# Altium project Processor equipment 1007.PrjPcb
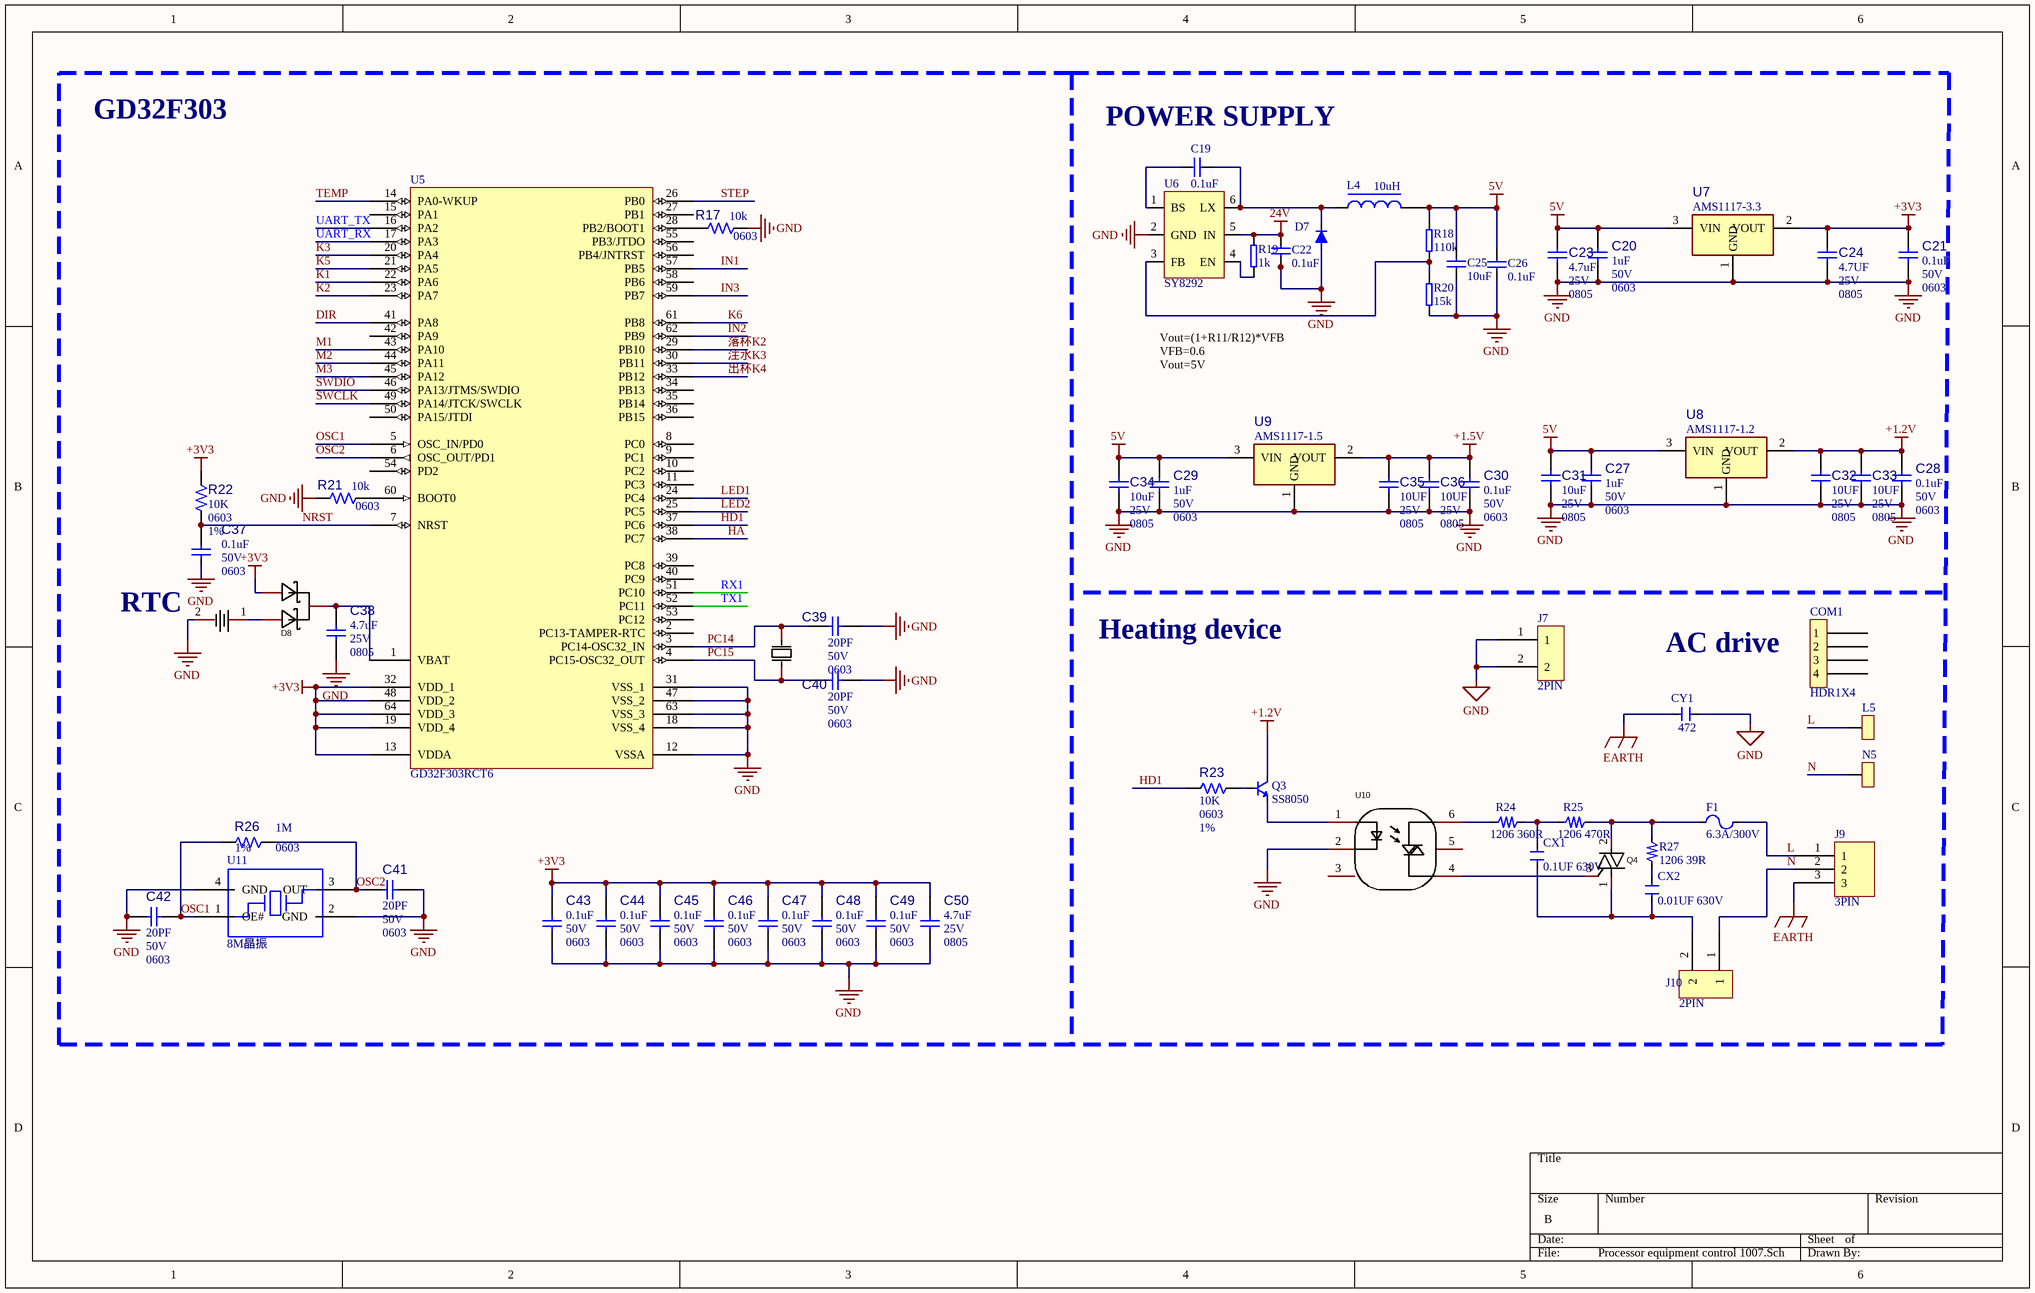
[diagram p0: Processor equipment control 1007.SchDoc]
3 sheets, 199 parts. Net scope: global (net labels, ports and power ports of the same name join across sheets).
Board file: Processor equipment 1101.PcbDoc
Sheets:
  Processor equipment control 1007.SchDoc
  Processor equipment drive 1007.SchDoc
  motor drive 1007.SchDoc

## Sheet Processor equipment control 1007.SchDoc
size B

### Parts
C19  0.1uF  [CAP_SMT_0805_T]
C20  value 1uF  Voltage: 50V  Package: 0603  [CAP_C_0603]  (hidden comment: Capacitor NP)
C21  value 0.1uF  Voltage: 50V  Package: 0603  [CAP_C_0603]  (hidden comment: Capacitor NP)
C22  0.1uF  [CAP_SMT_0805_T]
C23  value 4.7uF  Voltage: 25V  Package: 0805  [CAP_C_0805]  (hidden comment: Capacitor NP)
C24  value 4.7UF  Voltage: 25V  Package: 0805  [CAP_C_0805]  (hidden comment: Capacitor NP)
C25  10uF  [CAP_SMT_0805_T]
C26  0.1uF  [CAP_SMT_0805_T]
C27  value 1uF  Voltage: 50V  Package: 0603  [CAP_C_0603]  (hidden comment: Capacitor NP)
C28  value 0.1uF  Voltage: 50V  Package: 0603  [CAP_C_0603]  (hidden comment: Capacitor NP)
C29  value 1uF  Voltage: 50V  Package: 0603  [CAP_C_0603]  (hidden comment: Capacitor NP)
C30  value 0.1uF  Voltage: 50V  Package: 0603  [CAP_C_0603]  (hidden comment: Capacitor NP)
C31  value 10uF  Voltage: 25V  Package: 0805  [CAP_C_0805]  (hidden comment: Capacitor NP)
C32  value 10UF  Voltage: 25V  Package: 0805  [CAP_C_0805]  (hidden comment: Capacitor NP)
C33  value 10UF  Voltage: 25V  Package: 0805  [CAP_C_0805]  (hidden comment: Capacitor NP)
C34  value 10uF  Voltage: 25V  Package: 0805  [CAP_C_0805]  (hidden comment: Capacitor NP)
C35  value 10UF  Voltage: 25V  Package: 0805  [CAP_C_0805]  (hidden comment: Capacitor NP)
C36  value 10UF  Voltage: 25V  Package: 0805  [CAP_C_0805]  (hidden comment: Capacitor NP)
C37  value 0.1uF  Voltage: 50V  Package: 0603  [CAP_C_0603]  (hidden comment: Capacitor NP)
C38  value 4.7uF  Voltage: 25V  Package: 0805  [CAP_C_0805]  (hidden comment: Capacitor NP)
C39  value 20PF  Voltage: 50V  Package: 0603  [CAP_C_0603]  (hidden comment: Capacitor NP)
C40  value 20PF  Voltage: 50V  Package: 0603  [CAP_C_0603]  (hidden comment: Capacitor NP)
C41  value 20PF  Voltage: 50V  Package: 0603  [CAP_C_0603]  (hidden comment: Capacitor NP)
C42  value 20PF  Voltage: 50V  Package: 0603  [CAP_C_0603]  (hidden comment: Capacitor NP)
C43  value 0.1uF  Voltage: 50V  Package: 0603  [CAP_C_0603]  (hidden comment: Capacitor NP)
C44  value 0.1uF  Voltage: 50V  Package: 0603  [CAP_C_0603]  (hidden comment: Capacitor NP)
C45  value 0.1uF  Voltage: 50V  Package: 0603  [CAP_C_0603]  (hidden comment: Capacitor NP)
C46  value 0.1uF  Voltage: 50V  Package: 0603  [CAP_C_0603]  (hidden comment: Capacitor NP)
C47  value 0.1uF  Voltage: 50V  Package: 0603  [CAP_C_0603]  (hidden comment: Capacitor NP)
C48  value 0.1uF  Voltage: 50V  Package: 0603  [CAP_C_0603]  (hidden comment: Capacitor NP)
C49  value 0.1uF  Voltage: 50V  Package: 0603  [CAP_C_0603]  (hidden comment: Capacitor NP)
C50  value 4.7uF  Voltage: 25V  Package: 0805  [CAP_C_0805]  (hidden comment: Capacitor NP)
COM1  HDR1X4  [AC220v-24v]
CX1  0.1UF 630V  [C13*4*10_0.9]
CX2  0.01UF 630V  [C13*4*10_0.9]
CY1  472  [C9*6*7.5]
D7  US1K  [SMA-R]  (value not drawn)
D8  BAT54C-7-F  [SOT23-R-R]  (value not drawn)
F1  6.3A/300V  [FUSE_8.4*4.3_5.08_0.6]
J7  2PIN  [散热器]
J8  CR1220-2  [CR2032-6]  (value not drawn)
J9  3PIN  [HB-9500-3P]
J10  2PIN  [DG/KF128-2P]
L4  100016336  [100016336_SS_B]  (value not drawn)
L5  (no value)  [PAD_1.8]
N5  (no value)  [PAD_1.8]
Q3  SS8050  [SOT23-L-R]
Q4  BT138-800E  [TO-220-3_L10.0-W4.5-P2.54-L]  (value not drawn)
R17  value 10k  Package: 0603  [RES_C_0603]  (hidden comment: Resistor)
R18  110k  [RES_SMT_0805_T]
R19  1k  [RES_SMT_0805_T]
R20  15k  [RES_SMT_0805_T]
R21  value 10k  Package: 0603  [RES_C_0603]  (hidden comment: Resistor)
R22  value 10K  Package: 0603  Tolerance: 1%  [RES_C_0603]  (hidden comment: Resistor)
R23  value 10K  Package: 0603  Tolerance: 1%  [RES_C_0603]  (hidden comment: Resistor)
R24  1206 360R  [1206(3216)-R]
R25  1206 470R  [1206(3216)-R]
R26  value 1M  Package: 0603  Tolerance: 1%  [RES_C_0603]  (hidden comment: Resistor)
R27  1206 39R  [1206(3216)-R]
U5  GD32F303RCT6  [LQFP64]
U6  SY8292  [SOT23_6]
U7  value AMS1117-3.3  [SOT223-R]  (hidden comment: MCP1754ST-5002ECB SOT-23A-3)
U8  value AMS1117-1.2  [SOT223-R]  (hidden comment: MCP1754ST-5002ECB SOT-23A-3)
U9  value AMS1117-1.5  [SOT223-R]  (hidden comment: MCP1754ST-5002ECB SOT-23A-3)
U10  MOC3020SM_C3014297  [SOP-6_L7.1-W6.5-P2.54-LS10.1-BL]  (value not drawn)
U11  8M晶振  [S3225A]
X1  X50328MSB2GI  [X3215-2P晶振]  (value not drawn)

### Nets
5V: C20.2 C23.2 C25.1 C26.1 C27.2 C29.2 C31.2 C34.2 L4.2 R18.1 U7.3(VIN) U8.3(VIN) U9.3(VIN)
24V: C22.1 R19.2 U6.5(IN)
+1.2V: C28.2 C32.2 C33.2 Q3.3(C) U8.2(VOUT)
+1.5V: C30.2 C35.2 C36.2 U9.2(VOUT)
+3V3: C21.2 C24.2 C43.2 C44.2 C45.2 C46.2 C47.2 C48.2 C49.2 C50.2 D8.1(A) R22.2 U5.13(VDDA) U5.19(VDD_4) U5.32(VDD_1) U5.48(VDD_2) U5.64(VDD_3) U7.2(VOUT)
EARTH: CY1.2 J9.3
GND: C20.1 C21.1 C22.2 C23.1 C24.1 C25.2 C26.2 C27.1 C28.1 C29.1 C30.1 C31.1 C32.1 C33.1 C34.1 C35.1 C36.1 C37.1 C38.1 C39.1 C40.1 C41.1 C42.2 C43.1 C44.1 C45.1 C46.1 C47.1 C48.1 C49.1 C50.1 CY1.1 D7.1 J7.1 J7.2 J8.2 R17.1 R20.1 R21.2 U5.12(VSSA) U5.18(VSS_4) U5.31(VSS_1) U5.47(VSS_2) U5.63(VSS_3) U6.2(GND) U7.1(GND) U8.1(GND) U9.1(GND) U10.2(CAT) U11.2(GND) U11.4(GND)
DIR: U5.41(PA8)
HA: U5.38(PC7)
HD1: R23.2 U5.37(PC6)
IN1: U5.57(PB5)
IN2: U5.62(PB9)
IN3: U5.59(PB7)
K1: U5.22(PA6)
K2: U5.23(PA7)
K3: U5.20(PA4)
K5: U5.21(PA5)
K6: U5.61(PB8)
L: F1.1 J9.1 L5.1
LED1: U5.24(PC4)
LED2: U5.25(PC5)
M1: U5.43(PA10)
M2: U5.44(PA11)
M3: U5.45(PA12)
N: J9.2 J10.1 N5.1
NRST: C37.2 R22.1 U5.7(NRST)
OSC1: C42.1 R26.2 U5.5(OSC_IN/PD0) U11.1(OE#)
OSC2: C41.2 R26.1 U5.6(OSC_OUT/PD1) U11.3(OUT)
PC14: C39.2 U5.3(PC14-OSC32_IN) X1.2(OSC2)
PC15: C40.2 U5.4(PC15-OSC32_OUT) X1.1(OSC1)
RX1: U5.51(PC10)
STEP: U5.26(PB0)
SWCLK: U5.49(PA14/JTCK/SWCLK)
SWDIO: U5.46(PA13/JTMS/SWDIO)
TEMP: U5.14(PA0-WKUP)
TX1: U5.52(PC11)
UART_RX: U5.17(PA3)
UART_TX: U5.16(PA2)
出杯K4: U5.33(PB12)
注水K3: U5.30(PB11)
落杯K2: U5.29(PB10)
NetC19_1: C19.1 D7.2 L4.1 U6.6(LX)
NetC19_2: C19.2 U6.1(BS)
NetC38_2: C38.2 D8.3(K) U5.1(VBAT)
NetCX1_1: CX1.1 R24.2 R25.1
NetCX1_2: CX1.2 CX2.2 J10.2 Q4.1(T1)
NetCX2_1: CX2.1 R27.1
NetD8_2: D8.2(A) J8.1
NetF1_2: F1.2 Q4.2(T2) R25.2 R27.2
NetQ3_1: Q3.1(B) R23.1
NetQ3_2: Q3.2(E) U10.1(AN)
NetQ4_3: Q4.3(G) U10.4(TERMINAL)
NetR17_2: R17.2 U5.28(PB2/BOOT1)
NetR18_2: R18.2 R20.2 U6.3(FB)
NetR19_1: R19.1 U6.4(EN)
NetR21_1: R21.1 U5.60(BOOT0)
NetR24_1: R24.1 U10.6(TERMINAL)

Not connected (* = marked no-connect by the designer): COM1 1 2 3 4; U5 2(PC13-TAMPER-RTC) 8(PC0) 9(PC1) 10(PC2) 11(PC3) 15(PA1) 27(PB1) 34(PB13) 35(PB14) 36(PB15) 39(PC8) 40(PC9) 42(PA9) 50(PA15/JTDI) 53(PC12) 54(PD2) 55(PB3/JTDO) 56(PB4/JNTRST) 58(PB6); U10 3(NC) 5(SUBSTRATE)

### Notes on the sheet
- GD32F303
- (near C19) POWER SUPPLY
- Vout=(1+R11/R12)*VFB
  VFB=0.6
  Vout=5V
- RTC
- Heating device
- AC drive

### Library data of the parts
C19 C22 C25 C26 = 100000401: R_贴片电容_104K_50V_X7R_0805
C20 C21 C27-C30 C37 C39-C49 = CAP2016: Capacitor; Manufacturer 1: AVX Corporation; Manufacturer Part Number 1: 06035C104K4Z4A; Description_: CAP CER 0.1uF 50V 10% X7R AEC-Q200 SMD 0603; Dev Tools Status: Design; Tolerance: 10%; Temperature Coeffcient: X7R; Type: Ceramic; Owner: Sam Charles; Populated: YES
C23 C24 C31-C36 C38 C50 = CAP1211: Capacitor; Manufacturer 1: AVX; Manufacturer Part Number 1: 08053C105K4Z2A; Description_: CAP CER 1uF 25V 10% X7R SMD 0805; Dev Tools Status: Production; Tolerance: 10%; Temperature Coeffcient: X7R; Type: Ceramic; Owner: Tad Ahlvers; Populated: YES
CX1 CX2 = 4711101100299: 电容; COMPONENT_KIND: Standard; PIN_COUNT: 2; SCHVIEW.SHOW: 1; MODEL: C42Q2473K4SC450; SUPP: 法拉电子; CRC: 3; NAM: 薄膜电容/C42Q2473K4SC450/法拉电子/300V/0.047μF/±
CY1 = 4711140200471: COMPONENT_KIND: Standard; PIN_COUNT: 2; SCHVIEW.SHOW: 1; MODEL: HME222MA3DW-F6001; SUPP: 万明电子; CRC: 3; NAM: 瓷片电容/HME222MA3DW-F6001/万明电子/250V/2200pF/±20%/Y5U/编带AI/RoHS
D7 = 4715102500027: 二极管; COMPONENT_KIND: Standard; PIN_COUNT: 2; F_ID: SMA; CRC: 3; SCHVIEW.SHOW: 1; SUPP: LITE-ON; NAM: 贴片型快恢复二极管/US1K/LITE-ON/800V/1A/编带卷装/无/SM
D8 = BAT54C-7-F: Manufacturer: DIODES(美台); Add into BOM: yes; Reverse Voltage (Vr): 30V; Average Rectified Current (Io): 200mA; Forward Voltage (Vf@If): 800mV@100mA
F1 = 4621200700163: 保险丝; COMPONENT_KIND: Standard; PIN_COUNT: 2; CRC: 3; SHOW: 1; F_508: NA; F_507: 10s; F_506: 260℃; F_505: 1级; F_89: A0; F_38: RoHS; F_35: 带引脚; F_281: 8.35mm×4.3mm; F_106: 2A; F_3: 300V; F_2: CONQUER
J8 = CR1220-2: Manufacturer: Q&J; Add into BOM: yes; Connector Type: 电池底座; Battery Type: CR1220
L4 = 100016336: R贴片工字电感4*4_10uHM_21T_0.21*148mΩ
L5 N5 = 1pinx1.8mm
Q3 = 4715205500018: BEC; COMPONENT_KIND: Standard; PIN_COUNT: 3; SCHVIEW.SHOW: 1; F_ID: SOT23-L; MODEL: BC847B; SUPP: PHILIPS; NAM: 贴片型通用三极管/BC847B/PHILIPS/45V/100mA/NPN型，硅
Q4 = BT138-800E: Manufacturer: KY(韩景元); Add into BOM: yes
R17 R21 = RSMT0139: Manufacturer 1: Panasonic; Manufacturer Part Number 1: ERJ-3EKF1002V; Tolerance: 1%; Description_: RES TKF 10k 1% 1/10W SMD 0603; Dev Tools Status: Production; Temperature Coeffcient: 100ppm/C; Power: 1/10W; Populated: Yes
R18 = 100000285: R_片阻_100KJ_1/8W_±100PPM/℃_0805
R19 = 100000289: R_片阻_1KJ_1/8W_±100PPM/℃_0805
R20 = 100025954: R_片阻_12KF_1/8W_±100PPM/℃_0805
R22 R23 R26 = RES1051: Manufacturer 1: Panasonic; Manufacturer Part Number 1: ERJ-3RQF3R3V; Description_: RES TKF 3.3R 1% 1/10W SMD 0603; Dev Tools Status: Production; Temperature Coeffcient: 200ppm/C; Power: 1/10W; Owner: Tad Ahlvers; Populated: YES
R24 R25 R27 = 4712101500957: Resistor; COMPONENT_KIND: Standard; PIN_COUNT: 2; F_ID: R1206; CRC: 3; SCHVIEW.SHOW: 1; MODEL: RMC 1206 1/4W 43K F; SUPP: TY-OHM; NAM: 贴片通用电阻/RMC 1206 1/4W 43K F/TY-OHM/43KΩ/0
U5 = GD32F303RxT6
U7-U9 = MIC9094: LDO; Manufacturer 1: Microchip Technology Inc; Manufacturer Part Number 1: MCP1754S-5002E/CB; Description_: MCHP ANALOG LDO 5V MCP1754S-5002E/CB SOT-23A-3; Dev Tools Status: Design; Owner: Octavian Stroe; Populated: YES
U10 = MOC3020SM_C3014297: Manufacturer: UMW(友台半导体); Add into BOM: yes
X1 = X50328MSB2GI: Manufacturer: YXC(扬兴晶振); Name: 8MHz; Add into BOM: yes; Crystal Type: 贴片无源晶振; Value: 8MHz; Frequency Tolerance: ±10ppm; Frequency Stability: ±50ppm; Load Capacitance: 20pF

## Sheet Processor equipment drive 1007.SchDoc
size B
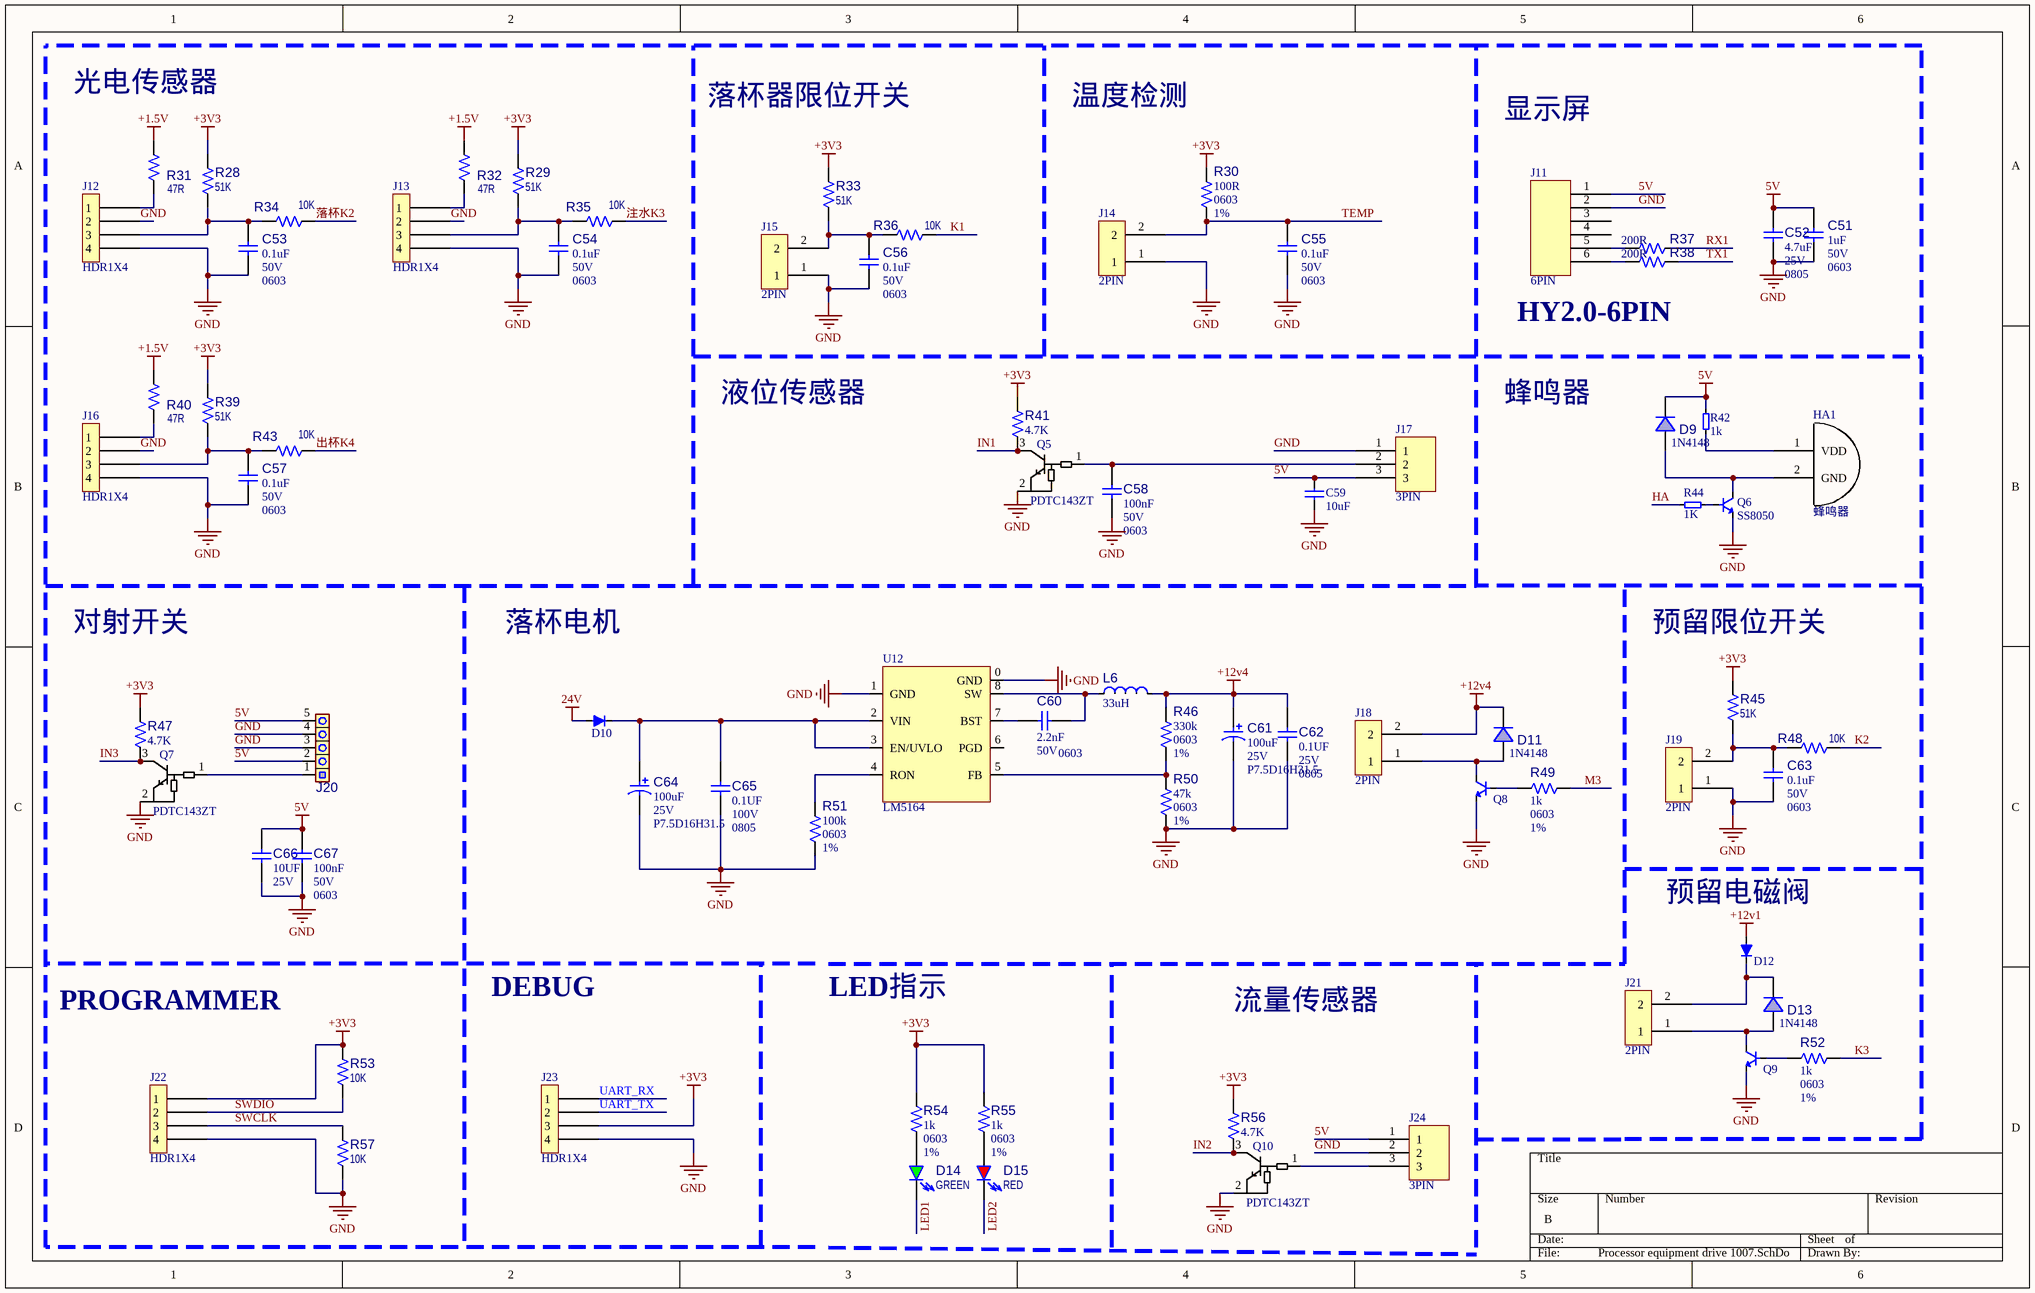
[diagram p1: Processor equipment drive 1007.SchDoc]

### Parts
C51  value 1uF  Voltage: 50V  Package: 0603  [CAP_C_0603]  (hidden comment: Capacitor NP)
C52  value 4.7uF  Voltage: 25V  Package: 0805  [CAP_C_0805]  (hidden comment: Capacitor NP)
C53  value 0.1uF  Voltage: 50V  Package: 0603  [CAP_C_0603]  (hidden comment: Capacitor NP)
C54  value 0.1uF  Voltage: 50V  Package: 0603  [CAP_C_0603]  (hidden comment: Capacitor NP)
C55  value 0.1uF  Voltage: 50V  Package: 0603  [CAP_C_0603]  (hidden comment: Capacitor NP)
C56  value 0.1uF  Voltage: 50V  Package: 0603  [CAP_C_0603]  (hidden comment: Capacitor NP)
C57  value 0.1uF  Voltage: 50V  Package: 0603  [CAP_C_0603]  (hidden comment: Capacitor NP)
C58  value 100nF  Voltage: 50V  Package: 0603  [CAP_C_0603]  (hidden comment: Capacitor NP)
C59  10uF  [CAP_SMT_0805_T]
C60  value 2.2nF  Voltage: 50V  Package: 0603  [CAP_C_0603]  (hidden comment: Capacitor NP)
C61  value 100uF  Voltage: 25V  Package: P7.5D16H31.5  [RB2.5/5_0.8]  (hidden comment: Capacitor POL)
C62  value 0.1UF  Voltage: 25V  Package: 0805  [CAP_C_0805]  (hidden comment: Capacitor NP)
C63  value 0.1uF  Voltage: 50V  Package: 0603  [CAP_C_0603]  (hidden comment: Capacitor NP)
C64  value 100uF  Voltage: 25V  Package: P7.5D16H31.5  [RB2.5/5_0.8]  (hidden comment: Capacitor POL)
C65  value 0.1UF  Voltage: 100V  Package: 0805  [CAP_C_0805]  (hidden comment: Capacitor NP)
C66  value 10UF  Voltage: 25V  [CAP_C_0805]  (hidden comment: Capacitor NP)
C67  value 100nF  Voltage: 50V  Package: 0603  [CAP_C_0603]  (hidden comment: Capacitor NP)
D9  value 1N4148  [SOD123-R]  (hidden comment: Diode Single)
D10  US1K  [SMA-R]  (value not drawn)
D11  value 1N4148  [SOD123-R]  (hidden comment: Diode Single)
D12  US1K  [SMA-R]  (value not drawn)
D13  value 1N4148  [SOD123-R]  (hidden comment: Diode Single)
D14  value GREEN  [LED_0603_GREEN]  (hidden comment: LED_green)
D15  value RED  [LED_0603_RED]  (hidden comment: LED_red)
HA1  蜂鸣器  [蜂鸣器6.5mm]
J11  6PIN  [HY2.0-6A]
J12  HDR1X4  [XH2.54mmX4P]
J13  HDR1X4  [XH2.54mmX4P]
J14  2PIN  [XH2.54mmX2P]
J15  2PIN  [XH2.54mmX2P]
J16  HDR1X4  [XH2.54mmX4P]
J17  3PIN  [XH2.54mm-3p]
J18  2PIN  [XH2.54mmX2P]
J19  2PIN  [XH2.54mmX2P]
J20  Header 1x5  [XH2.54MM-5P]  (value not drawn)
J21  2PIN  [XH2.54mmX2P]
J22  HDR1X4  [2.54mmx4]
J23  HDR1X4  [2.54mmx4]
J24  3PIN  [XH2.54mm-3p]
L6  value 33uH  [贴片电感]  (hidden comment: Inductor)
Q5  PDTC143ZT  [SOT23-L-R]
Q6  SS8050  [SOT23-L-R]
Q7  PDTC143ZT  [SOT23-L-R]
Q8  BCX56  [SOT89-R-R]  (value not drawn)
Q9  BCX56  [SOT89-R-R]  (value not drawn)
Q10  PDTC143ZT  [SOT23-L-R]
R28  value 51K  [RES_C_0603]  (hidden comment: Resistor)
R29  value 51K  [RES_C_0603]  (hidden comment: Resistor)
R30  value 100R  Package: 0603  Tolerance: 1%  [RES_C_0603]  (hidden comment: Resistor)
R31  value 47R  [RES_C_0805]  (hidden comment: Resistor)
R32  value 47R  [RES_C_0805]  (hidden comment: Resistor)
R33  value 51K  [RES_C_0603]  (hidden comment: Resistor)
R34  value 10K  [RES_C_0603]  (hidden comment: Resistor)
R35  value 10K  [RES_C_0603]  (hidden comment: Resistor)
R36  value 10K  [RES_C_0603]  (hidden comment: Resistor)
R37  200R  [RES_C_0603]
R38  200R  [RES_C_0603]
R39  value 51K  [RES_C_0603]  (hidden comment: Resistor)
R40  value 47R  [RES_C_0805]  (hidden comment: Resistor)
R41  value 4.7K  [RES_C_0603]  (hidden comment: Resistor)
R42  value 1k  [RES_SMT_0805_T]  (hidden comment: 100000285)
R43  value 10K  [RES_C_0603]  (hidden comment: Resistor)
R44  value 1K  [RES_SMT_0805_T]  (hidden comment: 100000285)
R45  value 51K  [RES_C_0603]  (hidden comment: Resistor)
R46  value 330k  Package: 0603  Tolerance: 1%  [RES_C_0603]  (hidden comment: Resistor)
R47  value 4.7K  [RES_C_0603]  (hidden comment: Resistor)
R48  value 10K  [RES_C_0603]  (hidden comment: Resistor)
R49  value 1k  Package: 0603  Tolerance: 1%  [0805(2012)-R]  (hidden comment: Resistor)
R50  value 47k  Package: 0603  Tolerance: 1%  [RES_C_0603]  (hidden comment: Resistor)
R51  value 100k  Package: 0603  Tolerance: 1%  [RES_C_0603]  (hidden comment: Resistor)
R52  value 1k  Package: 0603  Tolerance: 1%  [0805(2012)-R]  (hidden comment: Resistor)
R53  value 10K  [RES_C_0603]  (hidden comment: Resistor)
R54  value 1k  Package: 0603  Tolerance: 1%  [RES_C_0603]  (hidden comment: Resistor)
R55  value 1k  Package: 0603  Tolerance: 1%  [RES_C_0603]  (hidden comment: Resistor)
R56  value 4.7K  [RES_C_0603]  (hidden comment: Resistor)
R57  value 10K  [RES_C_0603]  (hidden comment: Resistor)
U12  LM5164  [SOIC-8-EP]

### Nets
5V: C51.2 C52.2 C59.1 C66.2 C67.1 D9.2(K) J11.1 J17.3 J20.2(P2) J20.5(P5) J24.1 R42.1
24V: D10.1
+1.5V: R31.2 R32.2 R40.2
+3V3: J22.1 J23.3 R28.2 R29.2 R30.2 R33.2 R39.2 R41.1 R45.2 R47.1 R53.1 R54.2 R55.2 R56.1
+12v1: D12.1
+12v4: C61.1 C62.2 D11.2(K) J18.2 L6.1(S) R46.2
GND: C51.1 C52.1 C53.1 C54.1 C55.1 C56.1 C57.1 C58.2 C59.2 C61.2 C62.1 C63.1 C64.2 C65.1 C66.1 C67.2 J11.2 J12.2 J12.4 J13.2 J13.4 J14.1 J15.1 J16.2 J16.4 J17.1 J19.1 J20.3(P3) J20.4(P4) J22.4 J23.4 J24.2 Q5.2 Q6.2(E) Q7.2 Q8.1(E) Q9.1(E) Q10.2 R50.1 R51.1 R57.2 U12.0(GND) U12.1(GND)
HA: R44.1
IN1: Q5.3 R41.2
IN2: Q10.3 R56.2
IN3: Q7.3 R47.2
K1: R36.1
K2: R48.1
K3: R52.1
LED1: D14.2(K)
LED2: D15.2(K)
M3: R49.1
RX1: R37.1
SWCLK: J22.3 R57.1
SWDIO: J22.2 R53.2
TEMP: C55.2 J14.2 R30.1
TX1: R38.1
UART_RX: J23.1
UART_TX: J23.2
出杯K4: R43.1
注水K3: R35.1
落杯K2: R34.1
NetC53_2: C53.2 J12.3 R28.1 R34.2
NetC54_2: C54.2 J13.3 R29.1 R35.2
NetC56_2: C56.2 J15.2 R33.1 R36.2
NetC57_2: C57.2 J16.3 R39.1 R43.2
NetC58_1: C58.1 J17.2 Q5.1
NetC60_1: C60.1 U12.7(BST)
NetC60_2: C60.2 L6.2(F) U12.8(SW)
NetC63_2: C63.2 J19.2 R45.1 R48.2
NetC64_1: C64.1 C65.2 D10.2 U12.2(VIN) U12.3(EN/UVLO)
NetD9_1: D9.1(A) HA1.2(GND) Q6.3(C)
NetD11_1: D11.1(A) J18.1 Q8.2(C)
NetD12_2: D12.2 D13.2(K) J21.2
NetD13_1: D13.1(A) J21.1 Q9.2(C)
NetD14_1: D14.1(A) R54.1
NetD15_1: D15.1(A) R55.1
NetHA1_1: HA1.1(VDD) R42.2
NetJ11_5: J11.5 R37.2
NetJ11_6: J11.6 R38.2
NetJ12_1: J12.1 R31.1
NetJ13_1: J13.1 R32.1
NetJ16_1: J16.1 R40.1
NetJ20_1: J20.1(P1) Q7.1
NetJ24_3: J24.3 Q10.1
NetQ6_1: Q6.1(B) R44.2
NetQ8_3: Q8.3(B) R49.2
NetQ9_3: Q9.3(B) R52.2
NetR46_1: R46.1 R50.2 U12.5(FB)
NetR51_2: R51.2 U12.4(RON)

Not connected (* = marked no-connect by the designer): J11 3 4; U12 6(PGD)

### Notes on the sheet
- 光电传感器
- 落杯器限位开关
- 温度检测
- 显示屏
- HY2.0-6PIN
- 液位传感器
- 蜂鸣器
- 对射开关
- 落杯电机
- 预留限位开关
- (near D12) 预留电磁阀
- PROGRAMMER
- DEBUG
- LED指示
- 流量传感器

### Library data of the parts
C51 C53-C57 C60 C63 = CAP2016: as C20 on sheet Processor equipment control 1007
C52 C62 C65 C66 = CAP1211: as C23 on sheet Processor equipment control 1007
C58 C67 = CAP1116: Manufacturer 1: KEMET; Manufacturer Part Number 1: C0603C472K5RACTU; Description_: CAP CER 4700pF 50V 10% X7R SMD 0603; Dev Tools Status: Production; Tolerance: 10%; Temperature Coeffcient: X7R; Type: Ceramic; Populated: YES; Owner: Miahi T(M91442)
C59 = 100000401: R_贴片电容_104K_50V_X7R_0805
C61 C64 = CAP2449: Capacitor; Manufacturer 1: Wurth Electronics; Manufacturer Part Number 1: 860040780019; Description_: CAP ALU 1200uF 63V 20% RAD P7.5D16H31.5; Dev Tools Status: Design; Tolerance: 20%; Type: Aluminum; Owner: Cristina Salanti; Populated: YES
D9 D11 D13 = DIODE0165: Manufacturer 1: Fairchild; Manufacturer Part Number 1: 1N4148WS; Description_: DIO RECT 1N4148 1V 150mA 100V SOD-323; Dev Tools Status: Production; Type: Rectifier Single; Forward Current: 150mA; Power: 200mW; Reverse Current: 5uA; Reverse Voltage: 100V; Populated: Yes
D10 D12 = 4715102500027: as D7 on sheet Processor equipment control 1007
D14 = DIODE1155: LED; Manufacturer 1: Lite-On Inc; Manufacturer Part Number 1: LTST-C191KGKT; Description_: DIO LED GREEN 2V 30mA 35mcd Clear SMD 0603; Dev Tools Status: Production; Type: LED Single; Forward Current: 30mA; Power: 75mW; Reverse Voltage: 5V; Owner: Tad Ahlvers; Populated: YES
D15 = DIODE1058: LED; Manufacturer 1: Lite-On; Manufacturer Part Number 1: LTST-C190EKT; Description_: DIO LED RED 2V 30mA 2mcd Clear SMD 0603; Dev Tools Status: Production; Type: LED Single; Forward Current: 30mA; Power: 100mW; Reverse Current: 100uA; Reverse Voltage: 5V; Owner: Tad Ahlvers; Populated: YES
J20 = CON0416: Manufacturer 1: FCI; Manufacturer Part Number 1: 68000-105HLF; Value: HDR-2.54 Male 1x5; Description_: CON HDR-2.54 Male 1x5 Gold 5.84MH TH VERT; Dev Tools Status: Production; Populated: Yes
L6 = IND1145: Manufacturer 1: WURTH ELEKTRONIK; Manufacturer Part Number 1: 7447779156; Description_: INDUCTOR 56uH 0.93A 20% SMD L7.3W7.3H4.5; Dev Tools Status: Design; Owner: Bogdan P (M91398); DCR: 0.35R; Saturation Current: 1.05A; RMS Current: 0.93A; Test Frequency: 1kHz; Populated: YES
Q5 Q7 Q10 = PDTC143ZT: 4.7k+47k NPN
Q6 = 4715205500018: as Q3 on sheet Processor equipment control 1007
Q8 Q9 = 4715205500100: ECB; COMPONENT_KIND: Standard; PIN_COUNT: 3; SCHVIEW.SHOW: 1; F_ID: SOT89-R; PCBVIEW.LAST_USER: admin; SUPP: NXP; NAM: 贴片型通用三极管/BCX56/NXP/80V/1A/NPN型/编带卷装/无/SO
R28 R29 R33-R36 R39 R43 R45 R48 R53 R57 = RES1406: Manufacturer 1: Yageo; Manufacturer Part Number 1: RC0603FR-072K4L; Tolerance: 1%; Description_: RES TKF 2.4K 1% 1/10W SMD 0603; Dev Tools Status: Production; Temperature Coeffcient: 100ppm/C; Power: 1/10W; Owner: Henry de Villiers; Populated: YES
R30 R49 R51 R52 = RSMT0349: Manufacturer 1: Vishay; Manufacturer Part Number 1: CRCW06033K30FKEA; Description_: RES TKF 3.3k 1% 1/10W SMD 0603; Dev Tools Status: Production; Temperature Coeffcient: 100ppm/C; Power: 1/10W; Populated: Yes; Voltage: 75V
R31 R32 R40 = RSMT0522: Manufacturer 1: Panasonic; Manufacturer Part Number 1: ERJ-6ENF3602V; Tolerance: 1%; Description_: RES TKF 36k 1% 1/8W SMD 0805; Dev Tools Status: Production; Voltage: 150V; Temperature Coeffcient: 100ppm/C; Power: 1/8W; Populated: Yes
R37 R38 = RES1406: Resistor; Manufacturer 1: Yageo; Manufacturer Part Number 1: RC0603FR-072K4L; Tolerance: 1%; Description_: RES TKF 2.4K 1% 1/10W SMD 0603; Dev Tools Status: Production; Temperature Coeffcient: 100ppm/C; Power: 1/10W; Owner: Henry de Villiers; Populated: YES
R41 R47 R56 = RES1130: Manufacturer 1: Panasonic; Manufacturer Part Number 1: ERJ-3EKF2201V; Tolerance: 1%; Description_: RES TKF 2.2k 1% 1/10W SMD 0603; Dev Tools Status: Production; Voltage: 75V; Temperature Coeffcient: 100ppm/C; Power: 1/10W; Populated: Yes; Owner: Bogdan P (M91398)
R42 R44 = 100000285: R_片阻_100KJ_1/8W_±100PPM/℃_0805
R46 R50 = RSMT0139: Manufacturer 1: Panasonic; Manufacturer Part Number 1: ERJ-3EKF1002V; Description_: RES TKF 10k 1% 1/10W SMD 0603; Dev Tools Status: Production; Temperature Coeffcient: 100ppm/C; Power: 1/10W; Populated: Yes
R54 R55 = RES1133: Manufacturer 1: MULTICOMP; Manufacturer Part Number 1: MC 0.063W 0603 1% 2K61; Description_: RES TKF 2.61k 1% 1/16W SMD 0603; Dev Tools Status: Production; Voltage: 50V; Temperature Coeffcient: 100ppm/C; Power: 1/16W; Owner: Mihai T(M91442); Populated: Yes

## Sheet motor drive 1007.SchDoc
size B
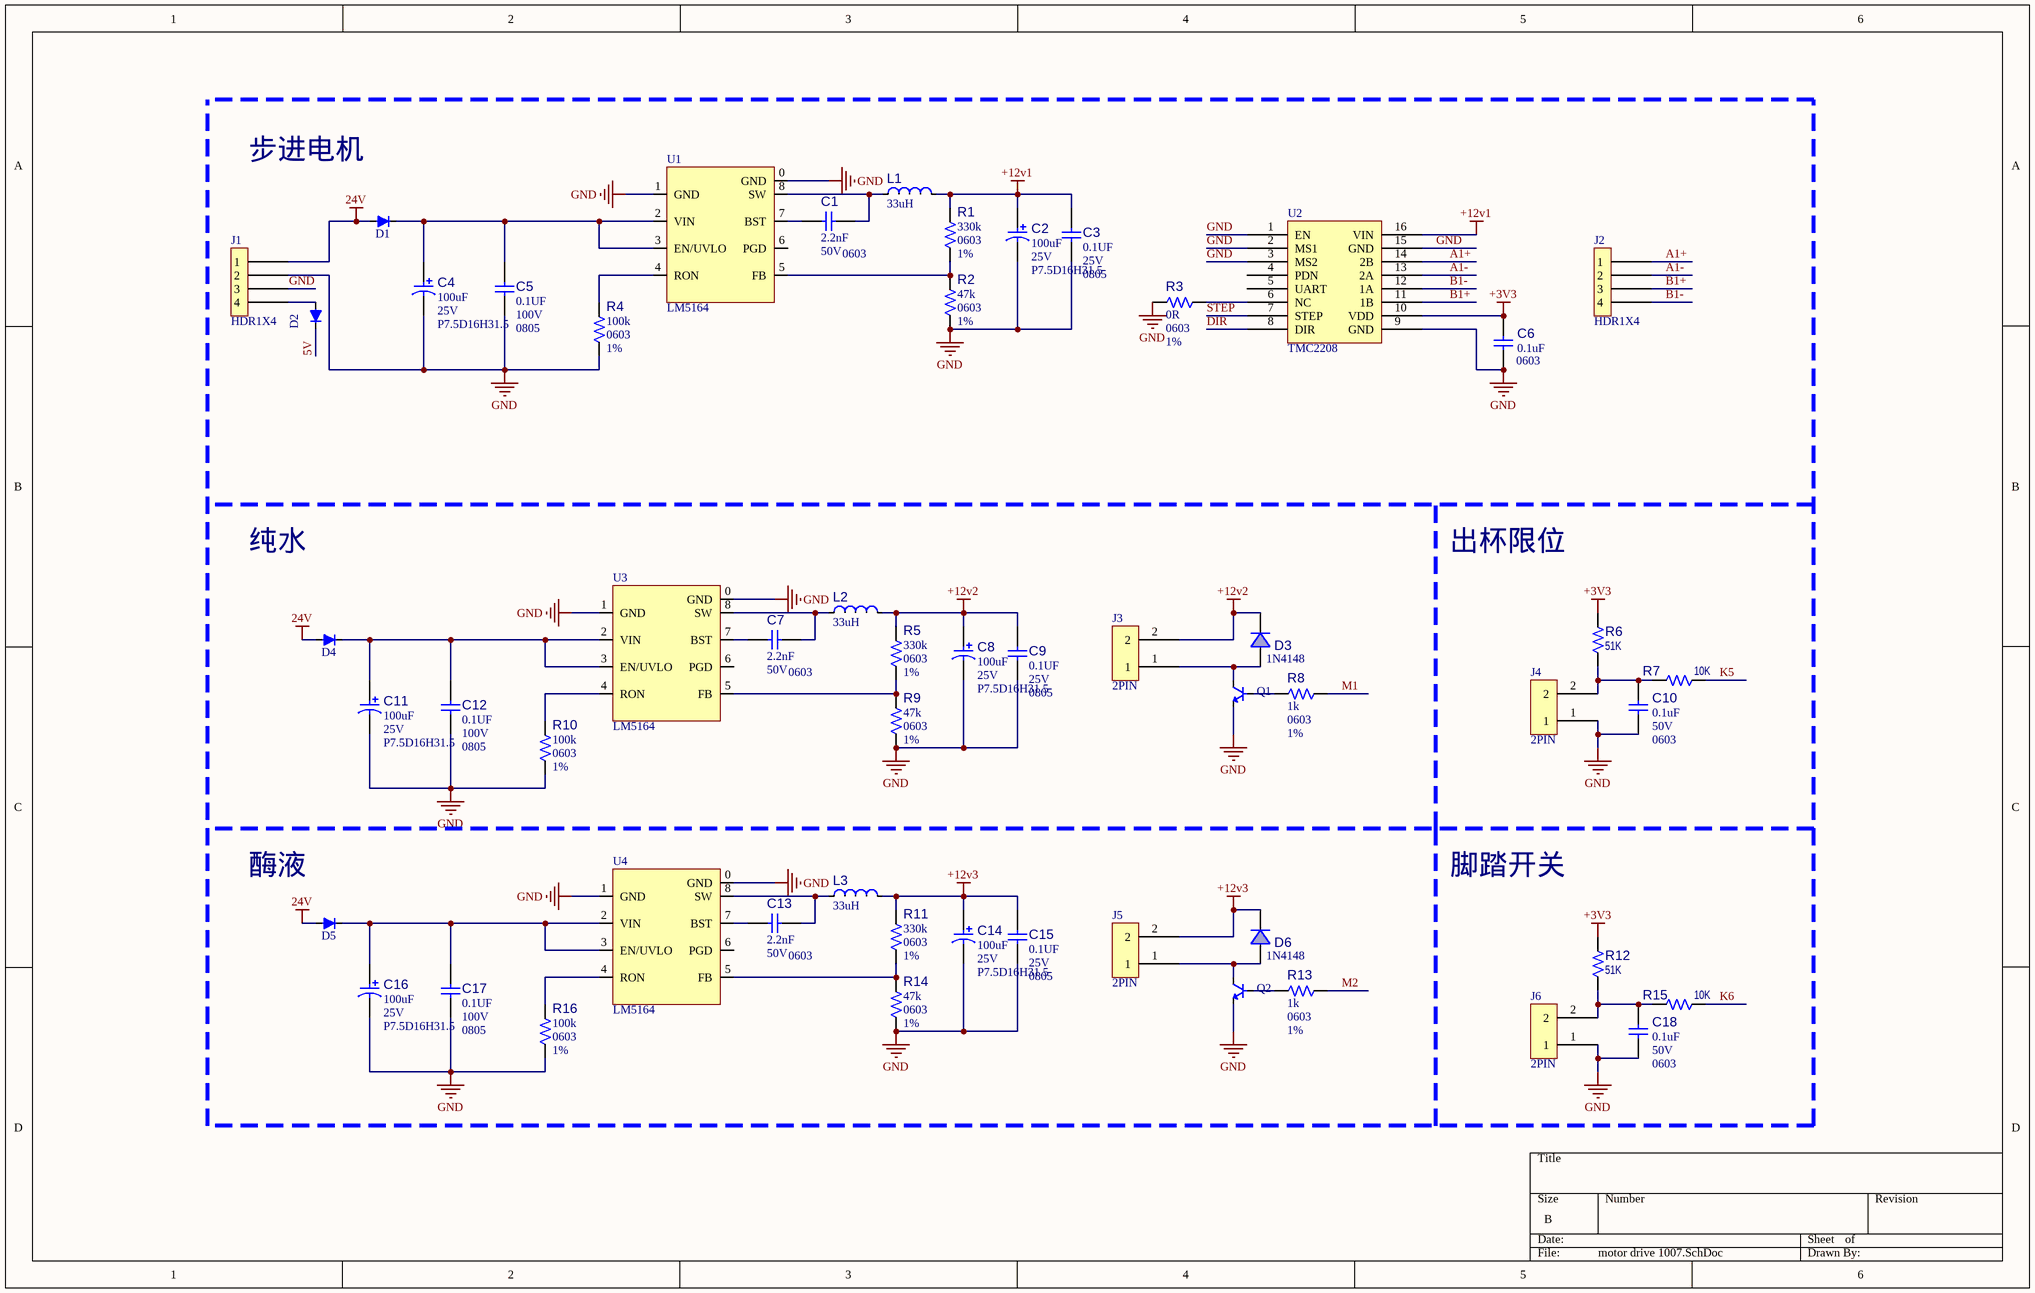
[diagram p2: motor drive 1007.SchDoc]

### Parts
C1  value 2.2nF  Voltage: 50V  Package: 0603  [CAP_C_0603]  (hidden comment: Capacitor NP)
C2  value 100uF  Voltage: 25V  Package: P7.5D16H31.5  [RB2.5/5_0.8]  (hidden comment: Capacitor POL)
C3  value 0.1UF  Voltage: 25V  Package: 0805  [CAP_C_0805]  (hidden comment: Capacitor NP)
C4  value 100uF  Voltage: 25V  Package: P7.5D16H31.5  [RB2.5/5_0.8]  (hidden comment: Capacitor POL)
C5  value 0.1UF  Voltage: 100V  Package: 0805  [CAP_C_0805]  (hidden comment: Capacitor NP)
C6  value 0.1uF  Package: 0603  [CAP_C_0603]  (hidden comment: Capacitor NP)
C7  value 2.2nF  Voltage: 50V  Package: 0603  [CAP_C_0603]  (hidden comment: Capacitor NP)
C8  value 100uF  Voltage: 25V  Package: P7.5D16H31.5  [RB2.5/5_0.8]  (hidden comment: Capacitor POL)
C9  value 0.1UF  Voltage: 25V  Package: 0805  [CAP_C_0805]  (hidden comment: Capacitor NP)
C10  value 0.1uF  Voltage: 50V  Package: 0603  [CAP_C_0603]  (hidden comment: Capacitor NP)
C11  value 100uF  Voltage: 25V  Package: P7.5D16H31.5  [RB2.5/5_0.8]  (hidden comment: Capacitor POL)
C12  value 0.1UF  Voltage: 100V  Package: 0805  [CAP_C_0805]  (hidden comment: Capacitor NP)
C13  value 2.2nF  Voltage: 50V  Package: 0603  [CAP_C_0603]  (hidden comment: Capacitor NP)
C14  value 100uF  Voltage: 25V  Package: P7.5D16H31.5  [RB2.5/5_0.8]  (hidden comment: Capacitor POL)
C15  value 0.1UF  Voltage: 25V  Package: 0805  [CAP_C_0805]  (hidden comment: Capacitor NP)
C16  value 100uF  Voltage: 25V  Package: P7.5D16H31.5  [RB2.5/5_0.8]  (hidden comment: Capacitor POL)
C17  value 0.1UF  Voltage: 100V  Package: 0805  [CAP_C_0805]  (hidden comment: Capacitor NP)
C18  value 0.1uF  Voltage: 50V  Package: 0603  [CAP_C_0603]  (hidden comment: Capacitor NP)
D1  US1K  [SMA-R]  (value not drawn)
D2  US1K  [SMA-R]  (value not drawn)
D3  value 1N4148  [SOD123-R]  (hidden comment: Diode Single)
D4  US1K  [SMA-R]  (value not drawn)
D5  US1K  [SMA-R]  (value not drawn)
D6  value 1N4148  [SOD123-R]  (hidden comment: Diode Single)
J1  HDR1X4  [XH2.54mmX4P]
J2  HDR1X4  [XH2.54mmX4P]
J3  2PIN  [XH2.54mmX2P]
J4  2PIN  [XH2.54mmX2P]
J5  2PIN  [XH2.54mmX2P]
J6  2PIN  [XH2.54mmX2P]
L1  value 33uH  [贴片电感]  (hidden comment: Inductor)
L2  value 33uH  [贴片电感]  (hidden comment: Inductor)
L3  value 33uH  [贴片电感]  (hidden comment: Inductor)
Q1  BCX56  [SOT89-R-R]  (value not drawn)
Q2  BCX56  [SOT89-R-R]  (value not drawn)
R1  value 330k  Package: 0603  Tolerance: 1%  [RES_C_0603]  (hidden comment: Resistor)
R2  value 47k  Package: 0603  Tolerance: 1%  [RES_C_0603]  (hidden comment: Resistor)
R3  value 0R  Package: 0603  Tolerance: 1%  [RES_C_0603]  (hidden comment: Resistor)
R4  value 100k  Package: 0603  Tolerance: 1%  [RES_C_0603]  (hidden comment: Resistor)
R5  value 330k  Package: 0603  Tolerance: 1%  [RES_C_0603]  (hidden comment: Resistor)
R6  value 51K  [RES_C_0603]  (hidden comment: Resistor)
R7  value 10K  [RES_C_0603]  (hidden comment: Resistor)
R8  value 1k  Package: 0603  Tolerance: 1%  [0805(2012)-R]  (hidden comment: Resistor)
R9  value 47k  Package: 0603  Tolerance: 1%  [RES_C_0603]  (hidden comment: Resistor)
R10  value 100k  Package: 0603  Tolerance: 1%  [RES_C_0603]  (hidden comment: Resistor)
R11  value 330k  Package: 0603  Tolerance: 1%  [RES_C_0603]  (hidden comment: Resistor)
R12  value 51K  [RES_C_0603]  (hidden comment: Resistor)
R13  value 1k  Package: 0603  Tolerance: 1%  [0805(2012)-R]  (hidden comment: Resistor)
R14  value 47k  Package: 0603  Tolerance: 1%  [RES_C_0603]  (hidden comment: Resistor)
R15  value 10K  [RES_C_0603]  (hidden comment: Resistor)
R16  value 100k  Package: 0603  Tolerance: 1%  [RES_C_0603]  (hidden comment: Resistor)
U1  LM5164  [SOIC-8-EP]
U2  TMC2208  [TMC2208]
U3  LM5164  [SOIC-8-EP]
U4  LM5164  [SOIC-8-EP]

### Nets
5V: D2.2
24V: D1.1 D4.1 D5.1 J1.1
+3V3: C6.2 R6.2 R12.2 U2.10(VDD)
+12v1: C2.1 C3.2 L1.1(S) R1.2 U2.16(VIN)
+12v2: C8.1 C9.2 D3.2(K) J3.2 L2.1(S) R5.2
+12v3: C14.1 C15.2 D6.2(K) J5.2 L3.1(S) R11.2
GND: C2.2 C3.1 C4.2 C5.1 C6.1 C8.2 C9.1 C10.1 C11.2 C12.1 C14.2 C15.1 C16.2 C17.1 C18.1 J1.2 J1.3 J4.1 J6.1 Q1.1(E) Q2.1(E) R2.1 R3.2 R4.1 R9.1 R10.1 R14.1 R16.1 U1.0(GND) U1.1(GND) U2.1(EN) U2.2(MS1) U2.3(MS2) U2.9(GND) U2.15(GND) U3.0(GND) U3.1(GND) U4.0(GND) U4.1(GND)
A1+: J2.1 U2.14(2B)
A1-: J2.2 U2.13(2A)
B1+: J2.3 U2.11(1B)
B1-: J2.4 U2.12(1A)
DIR: U2.8(DIR)
K5: R7.1
K6: R15.1
M1: R8.1
M2: R13.1
STEP: U2.7(STEP)
NetC1_1: C1.1 U1.7(BST)
NetC1_2: C1.2 L1.2(F) U1.8(SW)
NetC4_1: C4.1 C5.2 D1.2 U1.2(VIN) U1.3(EN/UVLO)
NetC7_1: C7.1 U3.7(BST)
NetC7_2: C7.2 L2.2(F) U3.8(SW)
NetC10_2: C10.2 J4.2 R6.1 R7.2
NetC11_1: C11.1 C12.2 D4.2 U3.2(VIN) U3.3(EN/UVLO)
NetC13_1: C13.1 U4.7(BST)
NetC13_2: C13.2 L3.2(F) U4.8(SW)
NetC16_1: C16.1 C17.2 D5.2 U4.2(VIN) U4.3(EN/UVLO)
NetC18_2: C18.2 J6.2 R12.1 R15.2
NetD2_1: D2.1 J1.4
NetD3_1: D3.1(A) J3.1 Q1.2(C)
NetD6_1: D6.1(A) J5.1 Q2.2(C)
NetQ1_3: Q1.3(B) R8.2
NetQ2_3: Q2.3(B) R13.2
NetR1_1: R1.1 R2.2 U1.5(FB)
NetR3_1: R3.1 U2.6(NC)
NetR4_2: R4.2 U1.4(RON)
NetR5_1: R5.1 R9.2 U3.5(FB)
NetR10_2: R10.2 U3.4(RON)
NetR11_1: R11.1 R14.2 U4.5(FB)
NetR16_2: R16.2 U4.4(RON)

Not connected (* = marked no-connect by the designer): U1 6(PGD); U2 4(PDN) 5(UART); U3 6(PGD); U4 6(PGD)

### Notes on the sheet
- 步进电机
- 纯水
- 出杯限位
- 酶液
- 脚踏开关

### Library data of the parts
C1 C6 C7 C10 C13 C18 = CAP2016: as C20 on sheet Processor equipment control 1007
C2 C4 C8 C11 C14 C16 = CAP2449: as C61 on sheet Processor equipment drive 1007
C3 C5 C9 C12 C15 C17 = CAP1211: as C23 on sheet Processor equipment control 1007
D1 D2 D4 D5 = 4715102500027: as D7 on sheet Processor equipment control 1007
D3 D6 = DIODE0165: as D9 on sheet Processor equipment drive 1007
L1-L3 = IND1145: as L6 on sheet Processor equipment drive 1007
Q1 Q2 = 4715205500100: as Q8 on sheet Processor equipment drive 1007
R1 R2 R5 R9 R11 R14 = RSMT0139: as R46 on sheet Processor equipment drive 1007
R3 R4 R8 R10 R13 R16 = RSMT0349: as R30 on sheet Processor equipment drive 1007
R6 R7 R12 R15 = RES1406: as R28 on sheet Processor equipment drive 1007

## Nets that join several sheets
5V: Processor equipment control 1007 (13 pins), Processor equipment drive 1007 (12 pins), motor drive 1007 (D2.2)
24V: Processor equipment control 1007 (C22.1 R19.2 U6.5), Processor equipment drive 1007 (D10.1), motor drive 1007 (D1.1 D4.1 D5.1 J1.1)
+1.5V: Processor equipment control 1007 (C30.2 C35.2 C36.2 U9.2), Processor equipment drive 1007 (R31.2 R32.2 R40.2)
+3V3: Processor equipment control 1007 (18 pins), Processor equipment drive 1007 (14 pins), motor drive 1007 (C6.2 R6.2 R12.2 U2.10)
+12v1: Processor equipment drive 1007 (D12.1), motor drive 1007 (5 pins)
GND: Processor equipment control 1007 (51 pins), Processor equipment drive 1007 (43 pins), motor drive 1007 (39 pins)
DIR: Processor equipment control 1007 (U5.41), motor drive 1007 (U2.8)
HA: Processor equipment control 1007 (U5.38), Processor equipment drive 1007 (R44.1)
IN1: Processor equipment control 1007 (U5.57), Processor equipment drive 1007 (Q5.3 R41.2)
IN2: Processor equipment control 1007 (U5.62), Processor equipment drive 1007 (Q10.3 R56.2)
IN3: Processor equipment control 1007 (U5.59), Processor equipment drive 1007 (Q7.3 R47.2)
K1: Processor equipment control 1007 (U5.22), Processor equipment drive 1007 (R36.1)
K2: Processor equipment control 1007 (U5.23), Processor equipment drive 1007 (R48.1)
K3: Processor equipment control 1007 (U5.20), Processor equipment drive 1007 (R52.1)
K5: Processor equipment control 1007 (U5.21), motor drive 1007 (R7.1)
K6: Processor equipment control 1007 (U5.61), motor drive 1007 (R15.1)
LED1: Processor equipment control 1007 (U5.24), Processor equipment drive 1007 (D14.2)
LED2: Processor equipment control 1007 (U5.25), Processor equipment drive 1007 (D15.2)
M1: Processor equipment control 1007 (U5.43), motor drive 1007 (R8.1)
M2: Processor equipment control 1007 (U5.44), motor drive 1007 (R13.1)
M3: Processor equipment control 1007 (U5.45), Processor equipment drive 1007 (R49.1)
RX1: Processor equipment control 1007 (U5.51), Processor equipment drive 1007 (R37.1)
STEP: Processor equipment control 1007 (U5.26), motor drive 1007 (U2.7)
SWCLK: Processor equipment control 1007 (U5.49), Processor equipment drive 1007 (J22.3 R57.1)
SWDIO: Processor equipment control 1007 (U5.46), Processor equipment drive 1007 (J22.2 R53.2)
TEMP: Processor equipment control 1007 (U5.14), Processor equipment drive 1007 (C55.2 J14.2 R30.1)
TX1: Processor equipment control 1007 (U5.52), Processor equipment drive 1007 (R38.1)
UART_RX: Processor equipment control 1007 (U5.17), Processor equipment drive 1007 (J23.1)
UART_TX: Processor equipment control 1007 (U5.16), Processor equipment drive 1007 (J23.2)
出杯K4: Processor equipment control 1007 (U5.33), Processor equipment drive 1007 (R43.1)
注水K3: Processor equipment control 1007 (U5.30), Processor equipment drive 1007 (R35.1)
落杯K2: Processor equipment control 1007 (U5.29), Processor equipment drive 1007 (R34.1)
